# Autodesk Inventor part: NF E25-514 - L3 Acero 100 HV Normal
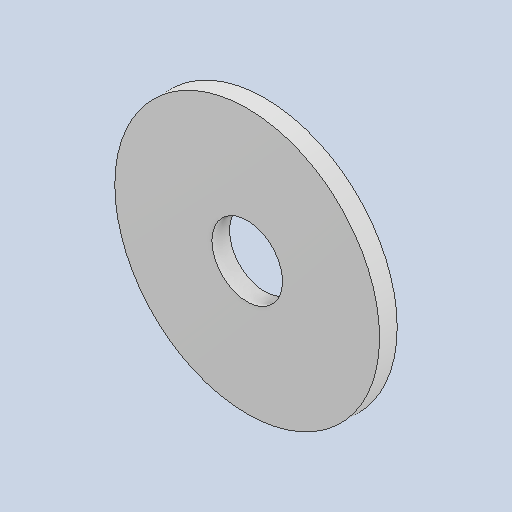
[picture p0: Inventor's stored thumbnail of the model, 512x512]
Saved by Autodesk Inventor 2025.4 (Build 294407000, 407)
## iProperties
Created: 2026-09
Part Number: NF E25-514 - L3 Acero 100 HV Normal
Material: Generic
Description: Arandela NF E25-514 - L3
Document SubType Name: Modeling
Designer: AdminForWorker
Density: 1 g/cm^3
Appearance: Default
Title: Arandela NF E25-514 - L3 Acero 100 HV Normal v1
Author: AdminForWorker
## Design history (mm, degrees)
feature "Body1"
body "Solid1"
